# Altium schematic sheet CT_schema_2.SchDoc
size 314 x 170 mm
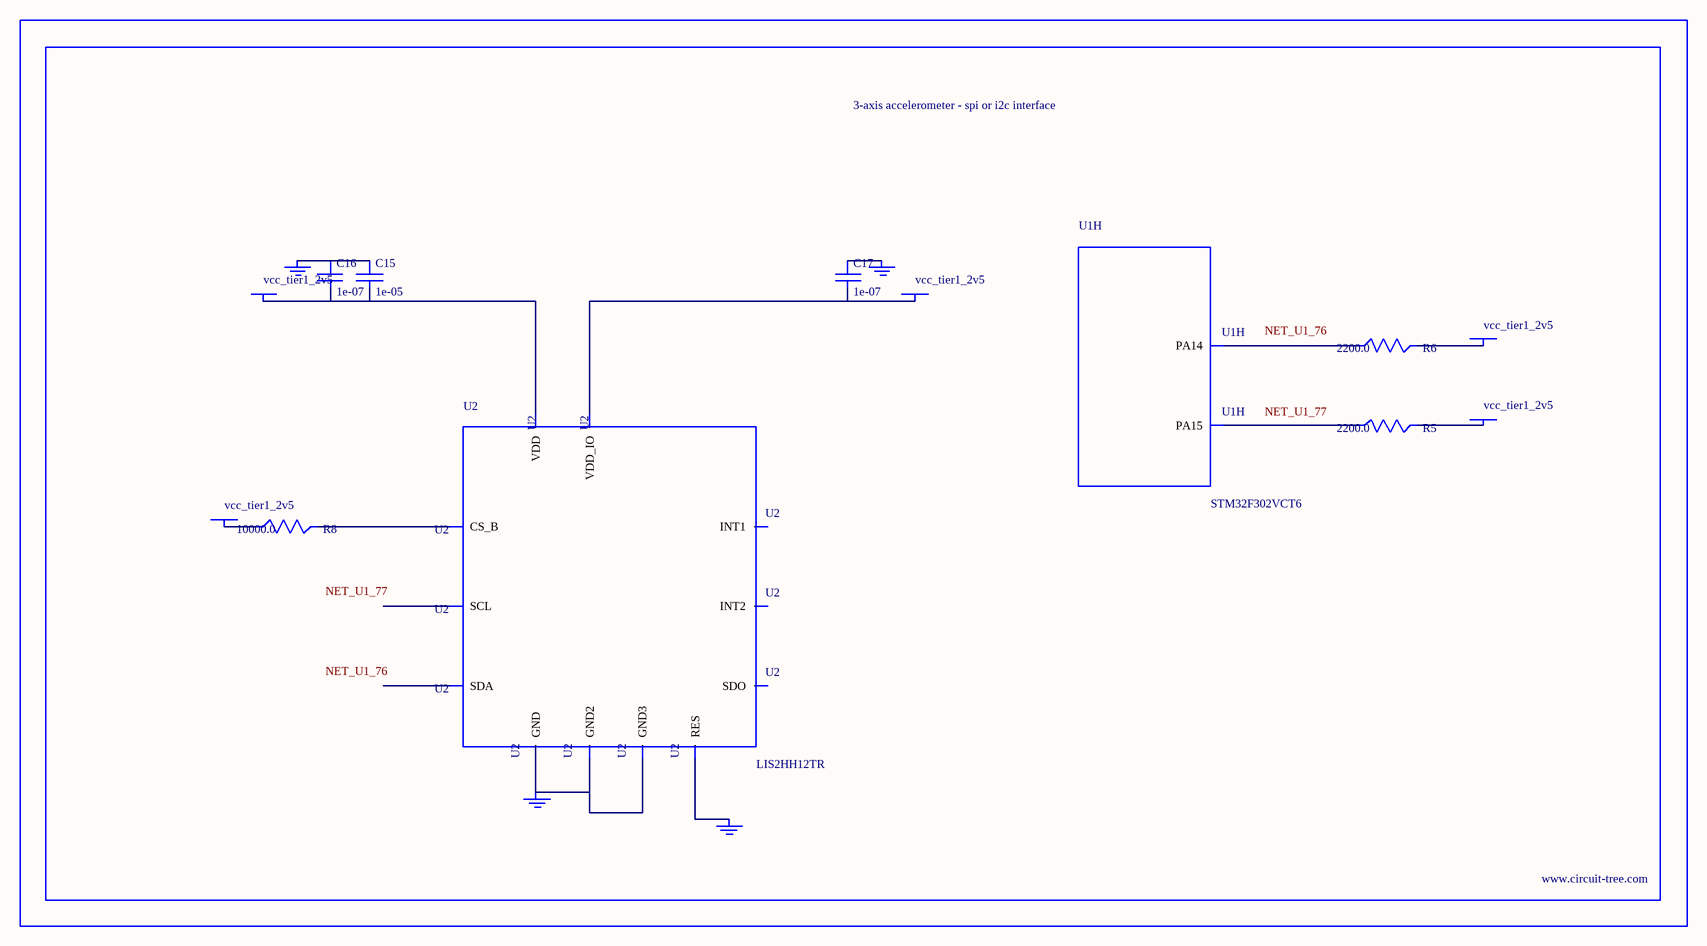
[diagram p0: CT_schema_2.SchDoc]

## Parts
BORDER1  (no value)
C15  1e-05  [C0805]
C16  1e-07  [C0402]
C17  1e-07  [C0402]
GND_INSTANCE_1_0  (no value)
GND_INSTANCE_1_1  (no value)
GND_INSTANCE_1_2  (no value)
GND_INSTANCE_1_3  (no value)
POWER_INSTANCE_1_0  vcc_tier1_2v5
POWER_INSTANCE_1_1  vcc_tier1_2v5
POWER_INSTANCE_1_2  vcc_tier1_2v5
POWER_INSTANCE_1_3  vcc_tier1_2v5
POWER_INSTANCE_1_4  vcc_tier1_2v5
R5  2200.0  [R0603]
R6  2200.0  [R0603]
R8  10000.0  [R0603]
U1  STM32F302VCT6  [LQFP100]  (part H of 9)
U2  LIS2HH12TR  [LGA-12]

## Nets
NetC15_1: C15.1 C16.1 GND_INSTANCE_1_1.0(GND)
NetC15_2: C15.2 C16.2 POWER_INSTANCE_1_1.0(PWR) U2.9(VDD)
NetC17_1: C17.1 GND_INSTANCE_1_2.0(GND)
NetC17_2: C17.2 POWER_INSTANCE_1_2.0(PWR) U2.10(VDD_IO)
NetGND_INSTANCE_1_0_0: GND_INSTANCE_1_0.0(GND) U2.5(RES)
NetGND_INSTANCE_1_3_0: GND_INSTANCE_1_3.0(GND) U2.6(GND) U2.7(GND2) U2.8(GND3)
NetPOWER_INSTANCE_1_0_0: POWER_INSTANCE_1_0.0(PWR) R8.1
NetPOWER_INSTANCE_1_3_0: POWER_INSTANCE_1_3.0(PWR) R6.2
NetPOWER_INSTANCE_1_4_0: POWER_INSTANCE_1_4.0(PWR) R5.2
NetR5_1: R5.1 U1.77(PA15)
NetR6_1: R6.1 U1.76(PA14)
NetR8_2: R8.2 U2.2(CS_B)

Not connected (* = marked no-connect by the designer): U2 1(SCL) 3(SDO) 4(SDA) 11(INT2) 12(INT1)

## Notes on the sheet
- Labels drawn without touching a wire or pin: NET_U1_76, NET_U1_77

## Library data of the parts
BORDER1 = BORDER_PAGE1
C15 = C0805C106K8RACTU
C16 C17 = C0402C104K3RACTU
GND_INSTANCE_1_0-GND_INSTANCE_1_3 = GND
POWER_INSTANCE_1_0-POWER_INSTANCE_1_4 = PWR
R5 R6 = RC0603JR-072K2L
R8 = RC0603JR-0710KL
